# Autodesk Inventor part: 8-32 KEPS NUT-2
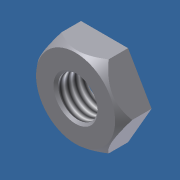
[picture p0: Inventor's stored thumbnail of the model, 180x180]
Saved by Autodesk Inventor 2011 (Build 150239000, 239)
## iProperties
Created: 2007-09
Part Number: 8-32 KEPS NUT-2
Document SubType Name: Modeling
Material: Stainless Steel
Density: 8.08 g/cm^3
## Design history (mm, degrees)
feature "Base1"
thread "Thread1" dims "d0" = 25.4, "d1" = 0
body "Solid1"
